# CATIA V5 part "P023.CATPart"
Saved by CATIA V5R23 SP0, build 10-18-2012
Part number: 05-LICP-T02-E-S07-P023
Definition: Volant De Manoeuvre
Description: Volant De Manoeuvre
Bounding box of the stored display mesh (mm): x 0 to 34, y -50 to 50, z -50 to 50
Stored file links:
  C:\wamp\www\COURS\CONCEPTION GMP1\TITRE 02-SEMESTRE 2\03-TP7-PRESSE MECANIQUE\eleve\P023.CATPart
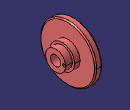
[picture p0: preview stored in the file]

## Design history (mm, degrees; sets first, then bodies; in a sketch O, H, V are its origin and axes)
Body1 (main body)
  Sketch1 on yz-plane, origin (0, 0, 0), H (0, 1, 0), V (0, 0, 1)
    circle A1 centre (0, 0) radius 50
    radius A1 = 50
  Pad1: profile Sketch1, direction (1, 0, 0), length 12
  Sketch2 on face of Pad1, origin (12, 0, 0), H (0, 1, 0), V (0, 0, 1)
    circle A1 centre (0, 0) radius 22
    radius A1 = 22
  Pad2: profile Sketch2, direction (1, 0, 0), length 10
  Sketch3 on face of Pad2, origin (22, 0, 0), H (0, 1, 0), V (0, 0, 1)
    circle A1 centre (0, 0) radius 18
    radius A1 = 18
  Pad3: profile Sketch3, direction (1, 0, 0), length 12
  Sketch4 on face of Pad1, origin (0, 0, 0), H (0, -1, 0), V (0, 0, 1)
    circle A1 centre (0, 0) radius 20
    radius A1 = 20
  Pocket1: profile Sketch4, direction (1, 0, 0), length 20
  Chamfer1: length 2, angle 45, on face of Pad1; edge [face of Pad1 | face of Pad1]
  Sketch5 on face of Pad3, origin (34, 0, 0), H (0, 1, 0), V (0, 0, 1)
    point P1 (0, 0)
    reference projected circle E1 centre (0, 0) radius 18 from edge [face of Pad3 | face of Pad3]
    concentricity: P1 E1
  Hole1: placed by Sketch5, at (34, 0, 0) direction (-1, 0, 0), diameter 18, through (limit type 6)
  Sketch6 on face of Pocket1, origin (20, 0, 0), H (0, 1, 0), V (0, 0, -1)
    point P1 (15, 0)
    distance V P1 = 15
    coincidence: H P1
  Hole2: placed by Sketch6, at (20, 15, 0) direction (1, 0, 0), diameter 5, through (limit type 6)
